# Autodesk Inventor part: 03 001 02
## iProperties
Shininess: 64.0
Length Units: 11269
Angle Units: 11279
Time Units: 11290
Mass Units: 11283
Length Display Precision: 3
Angle Display Precision: 2
Compacted: True
Part Number: 03 001 02
Document SubType Name: Modeling
Created: 2003-12
Material: Standard
Designer: HAH
Manufacturer: Standard
Standards Organization: Custom
Description: Wand A
Density: 0.0
Volumn: 0.0
Area: 0.0
PropertySet Name: Model Information
Control State: 0
Master: False
Checked Out: False
Author: HAH
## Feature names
1. Extrusion1
